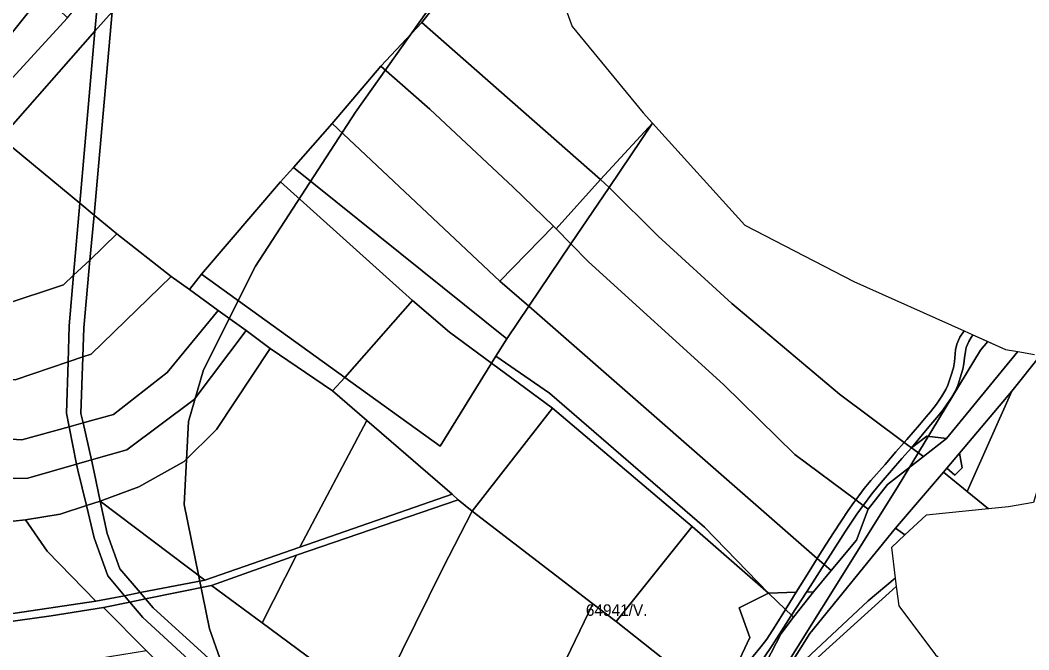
# Model space of a CAD drawing. Extents: x -521261 to -517465, y -1182764 to -1179456.
# Drawn here: x -518673.2 to -518235, y -1181572.2 to -1181298.5 of the extents above; entities that cross this region are included whole.
import ezdxf

# ---------------------------------------------------------------- set-up
doc = ezdxf.new("R2010")
doc.units = 0
for name, color, linetype in [('95560013', 7, 'Continuous'), ('95610013', 7, 'Continuous'), ('95630013', 7, 'Continuous'), ('95640013', 7, 'Continuous'), ('95660013', 7, 'Continuous')]:
    doc.layers.add(name, color=color, linetype=linetype)

msp = doc.modelspace()

# ---------------------------------------------------------------- linework, layer by layer
at = {"layer": '95560013'}
for points in [[(-518675.54, -1181274.63), (-518663.33, -1181287.08), (-518693.19, -1181324.53), (-518718.13, -1181347.7), (-518735.27, -1181357.29), (-518763.95, -1181367.17), (-518836.89, -1181372.83), (-518890.74, -1181379.2), (-519047.36, -1181389.95), (-519034.31, -1181361.29), (-518927.65, -1181352.54), (-518859.29, -1181344.94), (-518796.86, -1181341.76), (-518778.15, -1181339.19), (-518762.37, -1181334.9), (-518738.07, -1181325.54), (-518712.97, -1181307.58)], [(-518637.63, -1181279.33), (-518639.08, -1181284.96), (-518640.69, -1181303.28), (-518681.4, -1181349.69), (-518702.55, -1181373.11), (-518720.57, -1181388.36), (-518749.09, -1181398.29), (-518802.62, -1181403.53), (-518803.83, -1181388.28), (-518755.97, -1181382.48), (-518726.45, -1181370.33), (-518708.77, -1181358.68), (-518652.62, -1181297.59)], [(-518652.62, -1181297.59), (-518708.77, -1181358.68), (-518726.45, -1181370.33), (-518755.97, -1181382.48), (-518803.83, -1181388.28), (-518841.69, -1181390.76), (-518892.4, -1181397.12), (-519048.38, -1181403.77), (-519047.36, -1181389.95), (-518890.74, -1181379.2), (-518836.89, -1181372.83), (-518763.95, -1181367.17), (-518735.27, -1181357.29), (-518718.13, -1181347.7), (-518693.19, -1181324.53), (-518663.33, -1181287.08)], [(-518681.4, -1181349.69), (-518640.69, -1181303.28), (-518647.24, -1181378.13), (-518679.99, -1181350.96)], [(-518679.99, -1181350.96), (-518647.24, -1181378.13), (-518649.97, -1181409.3), (-518654.38, -1181413.51), (-518680.65, -1181422.21), (-518726.97, -1181421.02), (-518718.6, -1181389.5), (-518701.77, -1181375.89)], [(-518654.38, -1181413.51), (-518649.97, -1181409.3), (-518651.9, -1181431.4), (-518652.41, -1181447.08), (-518675.3, -1181454.82), (-518737.42, -1181451.29), (-518726.97, -1181421.02), (-518680.65, -1181422.21)], [(-518675.3, -1181454.82), (-518652.41, -1181447.08), (-518653.14, -1181469.35), (-518651.95, -1181475.2), (-518672.49, -1181480.9), (-518742.25, -1181476.5), (-518739.84, -1181458.33), (-518737.42, -1181451.29)], [(-518742.25, -1181476.5), (-518672.49, -1181480.9), (-518651.95, -1181475.2), (-518648.66, -1181491.51), (-518669.81, -1181497.63), (-518806.74, -1181500.53), (-518815.41, -1181498.2), (-518826.73, -1181497.94), (-518840.12, -1181498.94), (-518843.44, -1181480.79), (-518762.88, -1181478.17)], [(-518648.66, -1181491.51), (-518648.14, -1181494.08), (-518644.42, -1181509.49), (-518655.76, -1181513.23), (-518670.85, -1181515.74), (-518697.81, -1181518.58), (-518728.22, -1181520.3), (-518776.82, -1181516.87), (-518783.32, -1181511.62), (-518799.29, -1181502.53), (-518806.74, -1181500.53), (-518669.81, -1181497.63)], [(-518644.42, -1181509.49), (-518641.06, -1181523.42), (-518635.13, -1181539.99), (-518627.86, -1181548.63), (-518640.29, -1181551.02), (-518661.41, -1181529.26), (-518670.85, -1181515.74), (-518655.76, -1181513.23)], [(-518697.81, -1181518.58), (-518670.85, -1181515.74), (-518661.41, -1181529.26), (-518640.29, -1181551.02), (-518696.97, -1181559.36), (-518722.86, -1181561.13), (-518776.82, -1181516.87), (-518728.22, -1181520.3)], [(-518636.93, -1181553.72), (-518625.52, -1181551.41), (-518619.87, -1181558.14), (-518565.45, -1181608.23), (-518560.62, -1181612.85), (-518563.43, -1181613.7), (-518570.94, -1181616.73), (-518600.65, -1181590.04), (-518618.32, -1181572.55)]]:
    msp.add_lwpolyline(points, close=True, dxfattribs=at)
msp.add_lwpolyline([(-518696.97, -1181559.36), (-518640.29, -1181551.02), (-518627.86, -1181548.63), (-518625.52, -1181551.41), (-518636.93, -1181553.72), (-518659.72, -1181557.32), (-518687.87, -1181561.31)], dxfattribs=at)
at = {"layer": '95610013'}
for points in [[(-518618.91, -1181278.73), (-518468.13, -1181260.3), (-518498.65, -1181299.5), (-518516.46, -1181318.54), (-518537.66, -1181343.4), (-518554.51, -1181362.62), (-518557.46, -1181365.95), (-518560.15, -1181368.8), (-518594.4, -1181408.92), (-518599.62, -1181415.62), (-518607.63, -1181409.87), (-518631.22, -1181391.42), (-518641.12, -1181383.21), (-518633.23, -1181294.88)], [(-518398.47, -1181343.3), (-518358.32, -1181387.58), (-518310.97, -1181412.15), (-518263.14, -1181433.58), (-518263.41, -1181433.91), (-518264.9, -1181436.3), (-518266.24, -1181439.37), (-518266.86, -1181441.84), (-518267.3, -1181446.97), (-518267.78, -1181449.62), (-518268.86, -1181453.31), (-518270.19, -1181457.1), (-518271.06, -1181459.03), (-518272.77, -1181461.98), (-518275.15, -1181465.46), (-518277.7, -1181468.77), (-518279.52, -1181470.96), (-518282.53, -1181474.44), (-518288.05, -1181480.82), (-518289.09, -1181482.01), (-518317.29, -1181461.01), (-518364.01, -1181421.68), (-518396.09, -1181392.35), (-518417.38, -1181371.29)], [(-518554.51, -1181362.62), (-518461.77, -1181436.96), (-518466.48, -1181444.53), (-518468.37, -1181447.52), (-518486.7, -1181434.11), (-518502.68, -1181420.36), (-518560.15, -1181368.8), (-518557.46, -1181365.95)], [(-518594.4, -1181408.92), (-518560.15, -1181368.8), (-518502.68, -1181420.36), (-518532.09, -1181453.78)], [(-518417.38, -1181371.29), (-518396.09, -1181392.35), (-518364.01, -1181421.68), (-518317.29, -1181461.01), (-518289.09, -1181482.01), (-518292.71, -1181486.16), (-518297.47, -1181491.58), (-518303.64, -1181498.62), (-518306.46, -1181502.09), (-518308.9, -1181505.26), (-518310.17, -1181506.99), (-518336.65, -1181487.29), (-518367.67, -1181456.89), (-518426.34, -1181403.49), (-518433.91, -1181395.73)], [(-518631.22, -1181391.42), (-518642.96, -1181402.9), (-518641.12, -1181383.21)], [(-518642.96, -1181402.9), (-518631.22, -1181391.42), (-518607.63, -1181409.87), (-518642.36, -1181443.68), (-518645.93, -1181444.88), (-518645.49, -1181432.17)], [(-518433.91, -1181395.73), (-518426.34, -1181403.49), (-518367.67, -1181456.89), (-518336.65, -1181487.29), (-518310.17, -1181506.99), (-518311.01, -1181508.14), (-518313.46, -1181511.68), (-518316.56, -1181516.26), (-518319.86, -1181521.29), (-518322.98, -1181526.21), (-518326.45, -1181531.75), (-518326.88, -1181532.43), (-518452.27, -1181422.89)], [(-518599.62, -1181415.62), (-518594.4, -1181408.92), (-518532.09, -1181453.78), (-518537.45, -1181459.55), (-518564.54, -1181441.21), (-518575, -1181433.44), (-518587.17, -1181424.75)], [(-518599.62, -1181415.62), (-518587.17, -1181424.75), (-518609.35, -1181451.67), (-518632.7, -1181469.86), (-518645.87, -1181473.52), (-518646.77, -1181469.51), (-518645.93, -1181444.88), (-518642.36, -1181443.68), (-518607.63, -1181409.87)], [(-518502.68, -1181420.36), (-518486.7, -1181434.11), (-518468.37, -1181447.52), (-518490.77, -1181483.59), (-518532.09, -1181453.78)], [(-518575, -1181433.44), (-518597.65, -1181463.36), (-518626.88, -1181485.2), (-518642.25, -1181489.66), (-518645.87, -1181473.52), (-518632.7, -1181469.86), (-518609.35, -1181451.67), (-518587.17, -1181424.75)], [(-518452.27, -1181422.89), (-518326.88, -1181532.43), (-518330.44, -1181538.14), (-518334.33, -1181544.36), (-518336.05, -1181547.15), (-518348.05, -1181547.48), (-518375.96, -1181518.91), (-518443.2, -1181460.62), (-518466.48, -1181444.53), (-518461.77, -1181436.96)], [(-518564.54, -1181441.21), (-518587.85, -1181476.45), (-518601.97, -1181490.35), (-518621.65, -1181501.4), (-518638.43, -1181507.51), (-518641.06, -1181494.99), (-518642.25, -1181489.66), (-518626.88, -1181485.2), (-518597.65, -1181463.36), (-518575, -1181433.44)], [(-518260.11, -1181436.42), (-518259.28, -1181435.3), (-518245.14, -1181441.64), (-518239.78, -1181442.56), (-518270.78, -1181480.36), (-518279.33, -1181479.36), (-518285.98, -1181484.33), (-518278.42, -1181475.23), (-518274.99, -1181471.21), (-518272.42, -1181467.98), (-518270.4, -1181465.23), (-518268.39, -1181462.35), (-518267.01, -1181459.93), (-518265.9, -1181457.23), (-518263.73, -1181450.15), (-518263.28, -1181447.91), (-518262.97, -1181445.29), (-518262.57, -1181442.56), (-518262.19, -1181440.84), (-518261.09, -1181438.11)], [(-518537.45, -1181459.55), (-518522.59, -1181472.57), (-518551.66, -1181527.6), (-518592.9, -1181541.92), (-518638.43, -1181507.51), (-518621.65, -1181501.4), (-518601.97, -1181490.35), (-518587.85, -1181476.45), (-518564.54, -1181441.21)], [(-518537.45, -1181459.55), (-518532.09, -1181453.78), (-518490.77, -1181483.59), (-518468.37, -1181447.52), (-518441.93, -1181467.11), (-518476.82, -1181511.94), (-518482.96, -1181507.03), (-518485.57, -1181504.5), (-518522.59, -1181472.57)], [(-518466.48, -1181444.53), (-518443.2, -1181460.62), (-518375.96, -1181518.91), (-518348.05, -1181547.48), (-518381.22, -1181518.57), (-518441.93, -1181467.11), (-518468.37, -1181447.52)], [(-518230.37, -1181444.73), (-518220.1, -1181449.28), (-518219.98, -1181464.38), (-518232.93, -1181508.15), (-518243.76, -1181510.04), (-518252.51, -1181510.92), (-518261.84, -1181503.31), (-518242.44, -1181459.71)], [(-518242.44, -1181459.71), (-518261.84, -1181503.31), (-518272.08, -1181494.96), (-518270.6, -1181493.25), (-518267.19, -1181496.22), (-518264, -1181493.02), (-518265.05, -1181486.75)], [(-518476.82, -1181511.94), (-518441.93, -1181467.11), (-518381.22, -1181518.57), (-518414.21, -1181559.89), (-518424.37, -1181552.23)], [(-518485.57, -1181504.5), (-518551.66, -1181527.6), (-518522.59, -1181472.57)], [(-518279.33, -1181479.36), (-518270.78, -1181480.36), (-518280.81, -1181488.17), (-518285.98, -1181484.33)], [(-518285.98, -1181484.33), (-518280.81, -1181488.17), (-518296.43, -1181500.33), (-518304.73, -1181511.04), (-518306.93, -1181509.41), (-518306.81, -1181509.23), (-518303.15, -1181504.38), (-518299.1, -1181499.41), (-518290.21, -1181488.97)], [(-518272.08, -1181494.96), (-518261.84, -1181503.31), (-518252.51, -1181510.92), (-518279.66, -1181513.62), (-518288.8, -1181522.19), (-518292.92, -1181519.25)], [(-518482.96, -1181507.03), (-518553.18, -1181531.06), (-518590.03, -1181544.21), (-518618.68, -1181550.02), (-518621, -1181547.31), (-518592.9, -1181541.92), (-518551.66, -1181527.6), (-518485.57, -1181504.5)], [(-518635.46, -1181521.68), (-518638.43, -1181507.51), (-518592.9, -1181541.92), (-518621, -1181547.31), (-518629.92, -1181536.95)], [(-518476.82, -1181511.94), (-518489.59, -1181536.73), (-518519.06, -1181596.55), (-518521.74, -1181594.76), (-518568.08, -1181560.4), (-518553.18, -1181531.06), (-518482.96, -1181507.03)], [(-518304.73, -1181511.04), (-518309.8, -1181524.46), (-518320.86, -1181537.69), (-518323.88, -1181535.05), (-518321.03, -1181530.6), (-518314.57, -1181520.61), (-518309.67, -1181513.28), (-518306.93, -1181509.41)], [(-518476.82, -1181511.94), (-518424.37, -1181552.23), (-518462.54, -1181631.21), (-518499.78, -1181607.82), (-518519.06, -1181596.55), (-518489.59, -1181536.73)], [(-518381.22, -1181518.57), (-518348.05, -1181547.48), (-518360.77, -1181553.84), (-518356.15, -1181566.8), (-518363.84, -1181583.23), (-518369.82, -1181581.93), (-518373.71, -1181591.99), (-518414.21, -1181559.89)], [(-518590.03, -1181544.21), (-518553.18, -1181531.06), (-518568.08, -1181560.4)], [(-518320.86, -1181537.69), (-518328.61, -1181546.95), (-518331.57, -1181547.04), (-518329.99, -1181544.57), (-518323.88, -1181535.05)], [(-518618.68, -1181550.02), (-518590.03, -1181544.21), (-518568.08, -1181560.4), (-518521.74, -1181594.76), (-518535.82, -1181617.93), (-518540.13, -1181623.13), (-518546.52, -1181615.85), (-518560.78, -1181603.65), (-518615.36, -1181553.87)], [(-518292.56, -1181544.69), (-518291.45, -1181553.08), (-518275.51, -1181574.4), (-518250.99, -1181594.82), (-518241.23, -1181594.25), (-518243.36, -1181600.52), (-518249.18, -1181610.2), (-518264.94, -1181619.06), (-518301.2, -1181615.05), (-518318.67, -1181613.69), (-518322.27, -1181599.7), (-518331.35, -1181594), (-518347.44, -1181604.6), (-518346.6, -1181600.52), (-518340.75, -1181593.69), (-518343.97, -1181591.39), (-518323.21, -1181572.31)], [(-518636.93, -1181553.72), (-518618.32, -1181572.55), (-518661.16, -1181579.52), (-518719.19, -1181593.81), (-518719.53, -1181592.27), (-518723.26, -1181564.13), (-518687.87, -1181561.31), (-518659.72, -1181557.32)], [(-518414.21, -1181559.89), (-518373.71, -1181591.99), (-518377.91, -1181602.87), (-518383.59, -1181609.43), (-518386.34, -1181612.73), (-518389.22, -1181616.62), (-518391.62, -1181620.62), (-518392.94, -1181623.31), (-518394.86, -1181628.09), (-518399.35, -1181640.79), (-518403.02, -1181650.57), (-518407.53, -1181661.9), (-518407.83, -1181662.59), (-518408.48, -1181662.39), (-518428.88, -1181652.36), (-518462.54, -1181631.21), (-518424.37, -1181552.23)]]:
    msp.add_lwpolyline(points, close=True, dxfattribs=at)
at = {"layer": '95630013'}
msp.add_lwpolyline([(-518292.99, -1181541.03), (-518292.56, -1181544.69), (-518323.21, -1181572.31), (-518343.97, -1181591.39), (-518343, -1181586.61), (-518304.74, -1181550.83)], close=True, dxfattribs=at)
at = {"layer": '95640013'}
for points in [[(-518468.13, -1181260.3), (-518441.26, -1181279.93), (-518433.35, -1181301.32), (-518402.58, -1181338.76), (-518398.47, -1181343.3), (-518421.07, -1181367.82), (-518498.65, -1181299.5)], [(-518630.55, -1181275.53), (-518632.43, -1181285.85), (-518633.23, -1181294.88), (-518640.69, -1181303.28), (-518639.08, -1181284.96), (-518637.63, -1181279.33), (-518629.36, -1181269.07)], [(-518640.69, -1181303.28), (-518633.23, -1181294.88), (-518641.12, -1181383.21), (-518647.24, -1181378.13)], [(-518498.65, -1181299.5), (-518421.07, -1181367.82), (-518440.36, -1181389.16), (-518441.45, -1181388.12), (-518458.98, -1181371.1), (-518495.22, -1181337.25), (-518516.46, -1181318.54)], [(-518516.46, -1181318.54), (-518495.22, -1181337.25), (-518458.98, -1181371.1), (-518441.45, -1181388.12), (-518464.84, -1181411.92), (-518537.66, -1181343.4)], [(-518554.51, -1181362.62), (-518537.66, -1181343.4), (-518464.84, -1181411.92), (-518452.27, -1181422.89), (-518461.77, -1181436.96)], [(-518421.07, -1181367.82), (-518398.47, -1181343.3), (-518417.38, -1181371.29)], [(-518421.07, -1181367.82), (-518417.38, -1181371.29), (-518433.91, -1181395.73), (-518440.36, -1181389.16)], [(-518641.12, -1181383.21), (-518642.96, -1181402.9), (-518649.97, -1181409.3), (-518647.24, -1181378.13)], [(-518441.45, -1181388.12), (-518440.36, -1181389.16), (-518433.91, -1181395.73), (-518452.27, -1181422.89), (-518464.84, -1181411.92)], [(-518649.97, -1181409.3), (-518642.96, -1181402.9), (-518645.49, -1181432.17), (-518645.93, -1181444.88), (-518652.41, -1181447.08), (-518651.9, -1181431.4)], [(-518263.14, -1181433.58), (-518259.28, -1181435.3), (-518260.11, -1181436.42), (-518261.09, -1181438.11), (-518262.19, -1181440.84), (-518262.57, -1181442.56), (-518262.97, -1181445.29), (-518263.28, -1181447.91), (-518263.73, -1181450.15), (-518265.9, -1181457.23), (-518267.01, -1181459.93), (-518268.39, -1181462.35), (-518270.4, -1181465.23), (-518272.42, -1181467.98), (-518274.99, -1181471.21), (-518278.42, -1181475.23), (-518285.98, -1181484.33), (-518289.09, -1181482.01), (-518288.05, -1181480.82), (-518282.53, -1181474.44), (-518279.52, -1181470.96), (-518277.7, -1181468.77), (-518275.15, -1181465.46), (-518272.77, -1181461.98), (-518271.06, -1181459.03), (-518270.19, -1181457.1), (-518268.86, -1181453.31), (-518267.78, -1181449.62), (-518267.3, -1181446.97), (-518266.86, -1181441.84), (-518266.24, -1181439.37), (-518264.9, -1181436.3), (-518263.41, -1181433.91)], [(-518652.41, -1181447.08), (-518645.93, -1181444.88), (-518646.77, -1181469.51), (-518645.87, -1181473.52), (-518651.95, -1181475.2), (-518653.14, -1181469.35)], [(-518651.95, -1181475.2), (-518645.87, -1181473.52), (-518642.25, -1181489.66), (-518648.66, -1181491.51)], [(-518289.09, -1181482.01), (-518285.98, -1181484.33), (-518290.21, -1181488.97), (-518299.1, -1181499.41), (-518303.15, -1181504.38), (-518306.81, -1181509.23), (-518306.93, -1181509.41), (-518310.17, -1181506.99), (-518308.9, -1181505.26), (-518306.46, -1181502.09), (-518303.64, -1181498.62), (-518297.47, -1181491.58), (-518292.71, -1181486.16)], [(-518265.05, -1181486.75), (-518264, -1181493.02), (-518267.19, -1181496.22), (-518270.6, -1181493.25)], [(-518648.66, -1181491.51), (-518642.25, -1181489.66), (-518641.06, -1181494.99), (-518638.43, -1181507.51), (-518644.42, -1181509.49), (-518648.14, -1181494.08)], [(-518638.43, -1181507.51), (-518635.46, -1181521.68), (-518629.92, -1181536.95), (-518621, -1181547.31), (-518627.86, -1181548.63), (-518635.13, -1181539.99), (-518641.06, -1181523.42), (-518644.42, -1181509.49)], [(-518310.17, -1181506.99), (-518306.93, -1181509.41), (-518309.67, -1181513.28), (-518314.57, -1181520.61), (-518321.03, -1181530.6), (-518323.88, -1181535.05), (-518326.88, -1181532.43), (-518326.45, -1181531.75), (-518322.98, -1181526.21), (-518319.86, -1181521.29), (-518316.56, -1181516.26), (-518313.46, -1181511.68), (-518311.01, -1181508.14)], [(-518292.92, -1181519.25), (-518288.8, -1181522.19), (-518294.6, -1181527.65), (-518292.99, -1181541.03), (-518304.74, -1181550.83), (-518343, -1181586.61), (-518341.85, -1181583.76), (-518330.14, -1181565.02)], [(-518326.88, -1181532.43), (-518323.88, -1181535.05), (-518329.99, -1181544.57), (-518331.57, -1181547.04), (-518338.07, -1181557.14), (-518340.67, -1181554.63), (-518338.83, -1181551.64), (-518336.05, -1181547.15), (-518334.33, -1181544.36), (-518330.44, -1181538.14)], [(-518627.86, -1181548.63), (-518621, -1181547.31), (-518618.68, -1181550.02), (-518625.52, -1181551.41)], [(-518348.05, -1181547.48), (-518340.67, -1181554.63), (-518345.13, -1181561.85), (-518348.85, -1181567.48), (-518351.43, -1181570.85), (-518358.03, -1181578.9), (-518370.88, -1181594.65), (-518373.71, -1181591.99), (-518369.82, -1181581.93), (-518363.84, -1181583.23), (-518356.15, -1181566.8), (-518360.77, -1181553.84)], [(-518336.05, -1181547.15), (-518338.83, -1181551.64), (-518340.67, -1181554.63), (-518348.05, -1181547.48)], [(-518328.61, -1181546.95), (-518337.29, -1181557.9), (-518338.07, -1181557.14), (-518331.57, -1181547.04)], [(-518625.52, -1181551.41), (-518618.68, -1181550.02), (-518615.36, -1181553.87), (-518560.78, -1181603.65), (-518546.52, -1181615.85), (-518540.13, -1181623.13), (-518545.13, -1181629.18), (-518560.62, -1181612.85), (-518565.45, -1181608.23), (-518619.87, -1181558.14)], [(-518340.67, -1181554.63), (-518338.07, -1181557.14), (-518338.36, -1181557.58), (-518346.55, -1181570.23), (-518350.1, -1181575.69), (-518352.7, -1181579.27), (-518355.05, -1181582.12), (-518360.25, -1181588.07), (-518368.24, -1181597.13), (-518370.88, -1181594.65), (-518358.03, -1181578.9), (-518351.43, -1181570.85), (-518348.85, -1181567.48), (-518345.13, -1181561.85)], [(-518338.36, -1181557.58), (-518338.07, -1181557.14), (-518337.29, -1181557.9), (-518342.54, -1181565.05), (-518353.55, -1181586.4), (-518355.96, -1181592.03), (-518362.67, -1181594.83), (-518366.91, -1181598.39), (-518368.24, -1181597.13), (-518360.25, -1181588.07), (-518355.05, -1181582.12), (-518352.7, -1181579.27), (-518350.1, -1181575.69), (-518346.55, -1181570.23)]]:
    msp.add_lwpolyline(points, close=True, dxfattribs=at)
for points in [[(-518353.55, -1181586.4), (-518342.54, -1181565.05), (-518337.29, -1181557.9), (-518328.61, -1181546.95), (-518320.86, -1181537.69), (-518309.8, -1181524.46), (-518304.73, -1181511.04), (-518296.43, -1181500.33), (-518280.81, -1181488.17), (-518270.78, -1181480.36), (-518239.78, -1181442.56), (-518232.48, -1181443.8)], [(-518230.37, -1181444.73), (-518242.44, -1181459.71), (-518265.05, -1181486.75), (-518270.6, -1181493.25), (-518272.08, -1181494.96), (-518292.92, -1181519.25), (-518330.14, -1181565.02), (-518341.85, -1181583.76)]]:
    msp.add_lwpolyline(points, dxfattribs=at)
at = {"layer": '95660013'}
for points in [[(-518675.54, -1181274.63), (-518663.33, -1181287.08), (-518652.62, -1181297.59), (-518637.63, -1181279.33), (-518633.84, -1181274.63), (-518630.55, -1181275.53), (-518618.91, -1181278.73), (-518468.13, -1181260.3), (-518467.67, -1181260.24), (-518489.5, -1181285), (-518527.5, -1181338.5), (-518571, -1181405.5), (-518593.5, -1181450.5), (-518600, -1181473), (-518602, -1181509), (-518591, -1181563), (-518568, -1181628)], [(-518568, -1181628), (-518591, -1181563), (-518602, -1181509), (-518600, -1181473), (-518593.5, -1181450.5), (-518571, -1181405.5), (-518527.5, -1181338.5), (-518489.5, -1181285), (-518465.3, -1181257.55), (-518441.26, -1181279.93), (-518433.35, -1181301.32), (-518402.58, -1181338.76), (-518398.47, -1181343.3), (-518358.32, -1181387.58), (-518310.97, -1181412.15), (-518263.14, -1181433.58), (-518259.28, -1181435.3), (-518258.36, -1181435.71), (-518252.86, -1181438.18), (-518256, -1181442), (-518292, -1181501.5), (-518357, -1181605.5)], [(-518357, -1181605.5), (-518292, -1181501.5), (-518256, -1181442), (-518252.86, -1181438.18), (-518245.14, -1181441.64), (-518239.78, -1181442.56), (-518232.48, -1181443.8)], [(-518232.93, -1181508.15), (-518243.76, -1181510.04), (-518252.51, -1181510.92), (-518279.66, -1181513.62), (-518288.8, -1181522.19), (-518294.6, -1181527.65), (-518292.99, -1181541.03), (-518292.56, -1181544.69), (-518291.45, -1181553.08), (-518275.51, -1181574.4), (-518250.99, -1181594.82), (-518241.23, -1181594.25), (-518237.69, -1181594.04), (-518231.23, -1181593.65)]]:
    msp.add_lwpolyline(points, dxfattribs=at)

# ---------------------------------------------------------------- texts
msp.add_text('64941/V.', height=5, rotation=360, dxfattribs=at).set_placement((-518427.43, -1181557.39))

doc.saveas('drawing.dxf')
